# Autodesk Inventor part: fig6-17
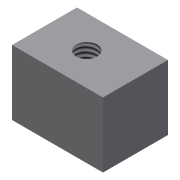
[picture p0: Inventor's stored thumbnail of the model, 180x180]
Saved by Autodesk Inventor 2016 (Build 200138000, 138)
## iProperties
Created: 2009-09
Part Number: fig6-17
Document SubType Name: Modeling
Designer: Sham
Density: 1 g/cm^3
Material: Generic
Appearance: Default
Author: Sham
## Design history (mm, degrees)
sketch "Sketch1"
  geometry: L1 (-28, 20)-(0, 20); L2 (0, 20)-(0, 0); L3 (0, 0)-(-28, 0); L4 (-28, 0)-(-28, 20)
  constraints: 8 end point, 2 parallel, 1 horizontal, 1 perpendicular
extrude "Extrusion1" new body sketch "Sketch1" distance "d0" = 20; taper "d1" = 0 deg
hole "Hole1" diameter "d4" = 6.401; stored, may be unused: countersink angle "d8" = 90 deg, drill point angle "d10" = 118 deg; dims "d2" = 10, "d3" = 15, "d5" = 6, "d6" = 12, "d7" = 3, "d9" = 15
body "Solid1"
